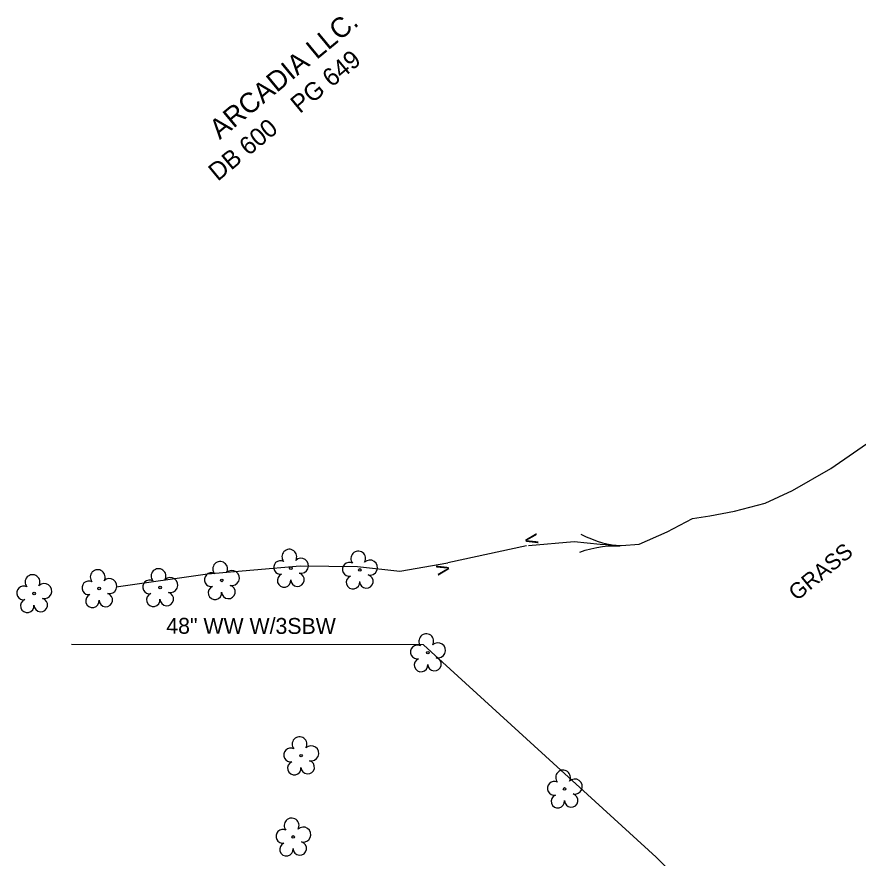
# Model space of a CAD drawing. Extents: x 1435573 to 1437263, y 981340 to 982884.
# Drawn here: x 1435652.2 to 1435863.7, y 981909.7 to 982121.3 of the extents above; entities that cross this region are included whole.
import ezdxf

# ---------------------------------------------------------------- set-up
doc = ezdxf.new("R2010")
doc.units = 0
for name, color, linetype in [('Exist Hydro Jurisdictional Stream or Body of Water', 7, 'Continuous'), ('Exist Hydro Stream Flow Arrow CELL', 7, 'Continuous'), ('Exist Hydro Stream or Body of Water', 7, 'Continuous'), ('Exist Other Culture Fence Line', 7, 'Continuous'), ('Exist Other Culture Fence Line Text', 7, 'Continuous'), ('Exist Property Deed Book Text', 7, 'Continuous'), ('Exist Property Owner Text', 7, 'Continuous'), ('Exist Structure Minor Culvert Topo', 7, 'Continuous'), ('Exist Structure Minor Culvert Topo Terminator', 7, 'Continuous'), ('Exist Vegetation Shrub Text', 7, 'Continuous'), ('Exist Vegetation Tree CELL', 7, 'Continuous')]:
    doc.layers.add(name, color=color, linetype=linetype)

msp = doc.modelspace()

# ---------------------------------------------------------------- linework, layer by layer
at = {"layer": 'Exist Hydro Jurisdictional Stream or Body of Water'}
for points in [[(1435780.8, 981988.37), (1435792.26, 981989.36), (1435798.84, 981988.67), (1435804.21, 981988.36), (1435808.63, 981988.71), (1435815.67, 981991.82), (1435822.07, 981995.16), (1435826.37, 981995.81), (1435832.56, 981996.94), (1435840.33, 981999), (1435847.15, 982002.15), (1435856.8, 982007.72)], [(1435677.18, 981977.96), (1435700.09, 981981.2), (1435723.44, 981983.24), (1435737.84, 981983.09), (1435748.47, 981981.93), (1435760.52, 981983.95)]]:
    msp.add_lwpolyline(points, dxfattribs=at)
at = {"layer": 'Exist Hydro Stream Flow Arrow CELL'}
msp.add_line((1435798.83, 981988.62), (1435798.83, 981988.62), dxfattribs=at)
for points in [[(1435794, 981991.23), (1435795.29, 981990.54), (1435796.68, 981989.99), (1435798.06, 981989.46), (1435799.45, 981989.05), (1435800.9, 981988.71), (1435802.37, 981988.45), (1435803.82, 981988.28)], [(1435793.69, 981986.67), (1435795.07, 981987.18), (1435796.52, 981987.54), (1435797.96, 981987.88), (1435799.39, 981988.1), (1435800.86, 981988.24), (1435802.36, 981988.3), (1435803.82, 981988.28)]]:
    msp.add_lwpolyline(points, dxfattribs=at)
at = {"layer": 'Exist Hydro Stream or Body of Water'}
msp.add_lwpolyline([(1435856.8, 982007.72), (1435868.19, 982015.59)], dxfattribs=at)
at = {"layer": 'Exist Other Culture Fence Line'}
msp.add_lwpolyline([(1435979.98, 982088.94), (1435959.09, 982053.91), (1435942.64, 982020.05), (1435877.1, 981880.75), (1435862.69, 981860.78), (1435812.93, 981909.96), (1435754.41, 981963.38), (1435665.92, 981963.47)], dxfattribs=at)
at = {"layer": 'Exist Structure Minor Culvert Topo'}
msp.add_lwpolyline([(1435780.33, 981988.26), (1435760.52, 981983.95)], dxfattribs=at)
at = {"layer": 'Exist Vegetation Tree CELL'}
for p, q in [((1435721.07, 981982.66), (1435721.07, 981982.66)), ((1435738.39, 981982.2), (1435738.39, 981982.2)), ((1435703.69, 981979.57), (1435703.69, 981979.57)), ((1435672.9, 981977.54), (1435672.9, 981977.54)), ((1435688.19, 981977.79), (1435688.19, 981977.79)), ((1435656.52, 981976.28), (1435656.52, 981976.28)), ((1435755.49, 981961.4), (1435755.49, 981961.4)), ((1435723.63, 981935.5), (1435723.63, 981935.5)), ((1435789.89, 981927.14), (1435789.89, 981927.14)), ((1435721.66, 981915.07), (1435721.66, 981915.07))]:
    msp.add_line(p, q, dxfattribs=at)
for centre in [(1435721.07, 981982.66), (1435738.39, 981982.2), (1435703.69, 981979.57), (1435672.9, 981977.54), (1435688.19, 981977.79), (1435656.52, 981976.28), (1435755.49, 981961.4), (1435723.63, 981935.5), (1435789.89, 981927.14), (1435721.66, 981915.07)]:
    msp.add_circle(centre, 0.326, dxfattribs=at)
for centre, radius, start, end in [((1435720.69, 981985.53), 1.86, 330.1651, 219.7134), ((1435738.01, 981985.07), 1.86, 330.1651, 219.7134), ((1435703.31, 981982.44), 1.86, 330.1651, 219.7134), ((1435718.47, 981982.81), 1.73, 62.6636, 279.3457), ((1435723.62, 981983.25), 1.9, 257.1011, 134.1999), ((1435735.79, 981982.35), 1.73, 62.6636, 279.3457), ((1435740.94, 981982.79), 1.9, 257.1011, 134.1999), ((1435672.51, 981980.41), 1.86, 330.1651, 219.7134), ((1435687.81, 981980.66), 1.86, 330.1651, 219.7134), ((1435701.09, 981979.72), 1.73, 62.6636, 279.3457), ((1435706.24, 981980.15), 1.9, 257.1011, 134.1999), ((1435722.75, 981979.76), 1.7, 181.2822, 74.56), ((1435656.13, 981979.15), 1.86, 330.1651, 219.7134), ((1435670.29, 981977.69), 1.73, 62.6636, 279.3457), ((1435675.44, 981978.13), 1.9, 257.1011, 134.1999), ((1435685.59, 981977.94), 1.73, 62.6636, 279.3457), ((1435690.74, 981978.38), 1.9, 257.1011, 134.1999), ((1435719.37, 981979.54), 1.69, 111.5671, 6.231), ((1435736.69, 981979.08), 1.69, 111.5671, 6.231), ((1435740.06, 981979.3), 1.7, 181.2822, 74.56), ((1435653.91, 981976.43), 1.73, 62.6636, 279.3457), ((1435659.06, 981976.86), 1.9, 257.1011, 134.1999), ((1435701.99, 981976.44), 1.69, 111.5671, 6.231), ((1435705.37, 981976.67), 1.7, 181.2822, 74.56), ((1435658.19, 981973.38), 1.7, 181.2822, 74.56), ((1435671.19, 981974.42), 1.69, 111.5671, 6.231), ((1435674.57, 981974.64), 1.7, 181.2822, 74.56), ((1435686.49, 981974.67), 1.69, 111.5671, 6.231), ((1435689.87, 981974.89), 1.7, 181.2822, 74.56), ((1435654.81, 981973.16), 1.69, 111.5671, 6.231), ((1435755.11, 981964.27), 1.86, 330.1651, 219.7134), ((1435752.89, 981961.55), 1.73, 62.6636, 279.3457), ((1435758.04, 981961.99), 1.9, 257.1011, 134.1999), ((1435753.79, 981958.28), 1.69, 111.5671, 6.231), ((1435757.17, 981958.5), 1.7, 181.2822, 74.56), ((1435723.25, 981938.37), 1.86, 330.1651, 219.7134), ((1435721.03, 981935.65), 1.73, 62.6636, 279.3457), ((1435726.18, 981936.09), 1.9, 257.1011, 134.1999), ((1435721.93, 981932.38), 1.69, 111.5671, 6.231), ((1435725.3, 981932.6), 1.7, 181.2822, 74.56), ((1435789.5, 981930.02), 1.86, 330.1651, 219.7134), ((1435787.28, 981927.3), 1.73, 62.6636, 279.3457), ((1435792.44, 981927.73), 1.9, 257.1011, 134.1999), ((1435788.18, 981924.02), 1.69, 111.5671, 6.231), ((1435791.56, 981924.24), 1.7, 181.2822, 74.56), ((1435721.27, 981917.95), 1.86, 330.1651, 219.7134), ((1435719.05, 981915.23), 1.73, 62.6636, 279.3457), ((1435724.21, 981915.66), 1.9, 257.1011, 134.1999), ((1435723.33, 981912.18), 1.7, 181.2822, 74.56), ((1435719.96, 981911.95), 1.69, 111.5671, 6.231)]:
    msp.add_arc(centre, radius, start, end, dxfattribs=at)

# ---------------------------------------------------------------- texts
at = {"layer": 'Exist Other Culture Fence Line Text'}
msp.add_text('48" WW W/3SBW', height=4, rotation=359.9381, dxfattribs=at).set_placement((1435689.76, 981966.15))
at = {"layer": 'Exist Property Deed Book Text'}
msp.add_text('DB 600    PG 649', height=4.5, rotation=39.5399, dxfattribs=at).set_placement((1435702.69, 982079.77))
at = {"layer": 'Exist Property Owner Text'}
msp.add_text('ARCADIA LLC.', height=5, rotation=39.5399, dxfattribs=at).set_placement((1435703.2, 982090.26))
at = {"layer": 'Exist Structure Minor Culvert Topo Terminator'}
for rotation, p in [(282.0331, (1435779.78, 981990.85)), (102.5148, (1435761.1, 981981.37))]:
    msp.add_text('v', height=4, rotation=rotation, dxfattribs=at).set_placement(p)
at = {"layer": 'Exist Vegetation Shrub Text'}
msp.add_text('GRASS', height=4, rotation=39.5399, dxfattribs=at).set_placement((1435848.27, 981974.26))

doc.saveas('drawing.dxf')
